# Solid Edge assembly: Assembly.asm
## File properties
Author: Deepak Maini
Template: Normal.asm
Last saved by: MYPC
Revision: 11
Application: Solid Edge
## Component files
Casting.par
Brasses.par
Cap.par
Bolt.par
Nut.par
Lock Nut.par
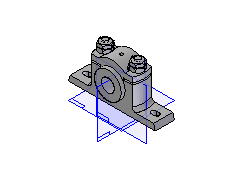
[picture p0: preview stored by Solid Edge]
